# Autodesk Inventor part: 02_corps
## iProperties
Created: 2002-11
Part Number: 02_corps
Material: Aluminum-6061
Document SubType Name: Modélisation
Designer: FIEVET
Control State: 0
Master: False
Checked Out: False
Shininess: 20.0
Length Units: 11269
Angle Units: 11279
Time Units: 11290
Mass Units: 11283
Length Display Precision: 3
Angle Display Precision: 2
Compacted: True
Density: 2.71
Volumn: 12.549919844309398
Area: 163.9387624029666
PropertySet Name: Model Information
Author: FIEVET
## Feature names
1. Extrusion1
2. Extrusion2
3. Lissage4
4. Lissage1
5. Réseau circulaire1 [Circular Pattern]
6. Lissage2
7. Extrusion3
8. Lissage3
9. Extrusion4
10. Extrusion5
11. Extrusion6
12. Extrusion7
13. Perçage1 [Hole]
14. Perçage2 [Hole]
15. Extrusion8
16. Extrusion9
17. Extrusion10
18. Extrusion11
19. Extrusion12
20. Extrusion13
21. Extrusion14
22. Extrusion15
23. Extrusion16
24. Congé1 [Fillet]
25. Extrusion17
